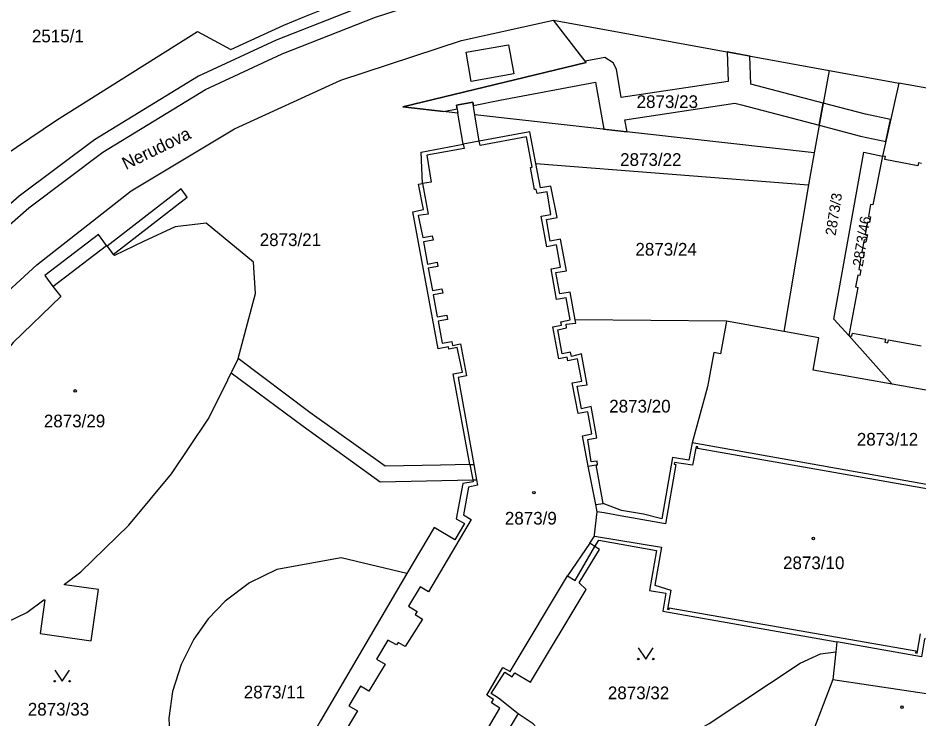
# Model space of a CAD drawing. Extents: x -756746 to -753363, y -1166406 to -1161727.
# Drawn here: x -756300.9 to -756180.3, y -1164964.7 to -1164870.8 of the extents above; entities that cross this region are included whole.
import ezdxf

# ---------------------------------------------------------------- set-up
doc = ezdxf.new("R2010")
doc.units = 0
for name, color, linetype in [('Hranice parcel', 7, 'Continuous'), ('Parcelní čísla', 7, 'Continuous'), ('Pop  PČ popisy', 7, 'Continuous'), ('Vnitřní kresba', 7, 'Continuous'), ('Věcná břemena k části', 7, 'Continuous'), ('Značky budov', 7, 'Continuous'), ('Značky kultur', 7, 'Continuous')]:
    doc.layers.add(name, color=color, linetype=linetype)

msp = doc.modelspace()

# ---------------------------------------------------------------- linework, layer by layer
at = {"layer": 'Hranice parcel'}
for p, q in [((-756241.55, -1164873.83), (-756229.25, -1164871.08)), ((-756229.25, -1164871.08), (-756192.35, -1164877.85)), ((-756192.35, -1164877.85), (-756194.33, -1164888.86)), ((-756183.02, -1164879.52), (-756185.21, -1164889.29)), ((-756155.37, -1164884.5), (-756183.02, -1164879.52)), ((-756240.05, -1164882.06), (-756242.23, -1164882.49)), ((-756242.23, -1164882.49), (-756242.06, -1164883.53)), ((-756239.78, -1164883.78), (-756240.05, -1164882.06)), ((-756241.36, -1164887.72), (-756242.06, -1164883.53)), ((-756239.21, -1164887.32), (-756239.78, -1164883.78)), ((-756194.33, -1164888.86), (-756239.78, -1164883.78)), ((-756232.42, -1164886.06), (-756239.21, -1164887.32)), ((-756231.6, -1164890.28), (-756232.42, -1164886.06)), ((-756194.33, -1164888.86), (-756195.09, -1164893.16)), ((-756230.97, -1164893.56), (-756231.6, -1164890.28)), ((-756231.6, -1164890.28), (-756195.09, -1164893.16)), ((-756195.09, -1164893.16), (-756198.4, -1164912.78)), ((-756226.33, -1164911.23), (-756227.02, -1164907.5)), ((-756226.25, -1164911.68), (-756226.33, -1164911.23)), ((-756206.1, -1164911.41), (-756226.33, -1164911.23)), ((-756198.4, -1164912.78), (-756206.1, -1164911.41)), ((-756189.7, -1164913.31), (-756183.9, -1164919.85)), ((-756240.44, -1164930.6), (-756240.07, -1164932.64)), ((-756191.3, -1164954.33), (-756191.45, -1164955.65)), ((-756191.45, -1164955.65), (-756191.87, -1164959.39)), ((-756191.87, -1164959.39), (-756194.46, -1164966.14)), ((-756191.87, -1164959.39), (-756173.81, -1164962.04))]:
    msp.add_line(p, q, dxfattribs=at)
for points in [[(-756332.73, -1164925.42), (-756326.95, -1164918.66), (-756327.49, -1164913.36), (-756312.07, -1164897.62), (-756304.74, -1164890.5), (-756295.77, -1164884.5), (-756276.91, -1164872.6), (-756272.47, -1164875.04), (-756265.36, -1164871.78), (-756262.76, -1164870.7), (-756260.3, -1164869.73), (-756257.97, -1164868.82), (-756255.56, -1164867.96), (-756253.1, -1164867.15), (-756240.81, -1164863.24), (-756239.69, -1164862.83), (-756238.72, -1164862.02)], [(-756242.06, -1164883.53), (-756249.44, -1164882.7), (-756224.89, -1164876.79), (-756229.25, -1164871.08)], [(-756326.38, -1164933.38), (-756310.7, -1164915.08), (-756298.41, -1164903.86), (-756285.81, -1164893.94), (-756271.95, -1164885.65), (-756257.71, -1164879.12), (-756241.55, -1164873.83)], [(-756192.35, -1164877.85), (-756184.46, -1164879.26), (-756183.02, -1164879.52)], [(-756240.44, -1164930.6), (-756242.68, -1164918.46), (-756241.45, -1164918.21), (-756242.16, -1164914.91), (-756243.26, -1164915.15), (-756243.32, -1164914.83), (-756244.68, -1164915.08), (-756248.07, -1164896.76), (-756246.65, -1164896.47), (-756247.31, -1164893.05), (-756246.77, -1164892.96), (-756246.97, -1164888.76), (-756241.36, -1164887.72)], [(-756189.7, -1164913.31), (-756191.73, -1164911.11), (-756187.68, -1164888.79), (-756185.21, -1164889.29)], [(-756185.21, -1164889.29), (-756186.5, -1164895.84), (-756186.8, -1164895.79), (-756187.09, -1164897.4), (-756186.8, -1164897.45), (-756186.94, -1164898.21), (-756187.23, -1164898.15), (-756187.53, -1164899.76), (-756187.23, -1164899.82), (-756187.37, -1164900.57), (-756187.66, -1164900.52), (-756187.96, -1164902.12), (-756187.66, -1164902.17), (-756187.8, -1164902.92), (-756188.09, -1164902.87), (-756188.39, -1164904.47), (-756188.09, -1164904.52), (-756188.23, -1164905.28), (-756188.52, -1164905.22), (-756188.82, -1164906.82), (-756188.52, -1164906.88), (-756189.7, -1164913.31)], [(-756179.98, -1164890.29), (-756180.37, -1164890.22), (-756180.45, -1164890.61), (-756184.89, -1164889.76), (-756184.81, -1164889.37), (-756185.21, -1164889.29)], [(-756240.44, -1164930.6), (-756244.37, -1164930.66), (-756251.8, -1164930.83), (-756261.87, -1164923.62), (-756271.47, -1164916.38), (-756269.15, -1164907.71), (-756269.4, -1164903.52), (-756275.75, -1164898.27), (-756279.9, -1164898.77), (-756284.16, -1164900.75), (-756288.03, -1164902.62), (-756288.18, -1164902.47), (-756278.28, -1164894.79), (-756279.08, -1164893.7), (-756289, -1164901.35), (-756289.08, -1164901.28), (-756290.18, -1164899.81), (-756297.35, -1164905.28), (-756296.26, -1164906.74), (-756295.22, -1164908.1), (-756301.6, -1164914.27), (-756307.34, -1164921.2), (-756312.21, -1164928.56), (-756314.71, -1164933.55)], [(-756227.02, -1164907.5), (-756228.39, -1164907.75), (-756228.93, -1164904.9), (-756227.53, -1164904.64), (-756228.31, -1164900.41), (-756229.68, -1164900.67), (-756230.18, -1164897.79), (-756228.77, -1164897.52), (-756229.59, -1164893.33), (-756230.97, -1164893.56)], [(-756222.59, -1164935.8), (-756223.54, -1164930.65), (-756223.38, -1164930.62), (-756223.41, -1164930.13), (-756224.22, -1164930.24), (-756224.67, -1164927.22), (-756223.43, -1164927.03), (-756224.19, -1164922.84), (-756225.51, -1164923.14), (-756226.09, -1164920.11), (-756224.74, -1164919.92), (-756225.51, -1164915.76), (-756226.86, -1164916.11), (-756226.96, -1164915.57), (-756228.09, -1164915.78), (-756228.68, -1164912.58), (-756227.49, -1164912.3), (-756227.54, -1164911.8), (-756226.25, -1164911.68)], [(-756206.1, -1164911.41), (-756206.91, -1164915.76), (-756207.78, -1164915.59), (-756208.63, -1164920.21), (-756210.69, -1164927.69)], [(-756183.9, -1164919.85), (-756194.49, -1164917.98), (-756193.73, -1164913.61), (-756198.4, -1164912.78)], [(-756189.7, -1164913.31), (-756189.3, -1164913.39), (-756189.23, -1164912.99), (-756184.81, -1164913.81), (-756184.88, -1164914.21), (-756184.5, -1164914.28), (-756184.42, -1164913.88), (-756180.03, -1164914.7)], [(-756312.02, -1164954.84), (-756307.85, -1164954.28), (-756299.75, -1164950.41), (-756297.47, -1164948.69), (-756297.37, -1164948.71), (-756297.99, -1164953.23), (-756291.13, -1164954.18), (-756290.16, -1164947.31), (-756294.71, -1164946.69), (-756294.7, -1164946.61), (-756292.53, -1164944.94), (-756286.1, -1164938.71), (-756280.39, -1164931.84), (-756275.49, -1164924.52), (-756273.31, -1164920.17), (-756272.42, -1164918.32), (-756262.77, -1164925.47), (-756252.46, -1164932.92), (-756240.07, -1164932.64)], [(-756160.13, -1164924.19), (-756163.99, -1164923.36), (-756183.9, -1164919.85)], [(-756210.69, -1164927.69), (-756211.13, -1164930.02), (-756213.31, -1164929.65), (-756214.73, -1164937.87), (-756217.2, -1164937.24), (-756220.16, -1164936.74), (-756222.59, -1164935.8)], [(-756167.95, -1164937.59), (-756176.44, -1164936.08), (-756176.04, -1164933.86), (-756210.69, -1164927.69)], [(-756240.07, -1164932.64), (-756240.02, -1164932.89), (-756241.37, -1164933.14), (-756242.26, -1164937.87), (-756241.18, -1164938.48), (-756242.47, -1164940.67), (-756245.24, -1164939.04), (-756248.89, -1164945.2)], [(-756223.72, -1164941.55), (-756224.4, -1164941.11), (-756223.78, -1164940.2), (-756223.76, -1164940.02), (-756223.42, -1164936.91), (-756223.6, -1164935.95), (-756222.59, -1164935.8)], [(-756223.72, -1164941.55), (-756223.19, -1164940.7), (-756215.47, -1164942.1), (-756216.38, -1164947.45), (-756214.21, -1164947.82), (-756214.63, -1164950.21), (-756191.3, -1164954.33)], [(-756233.96, -1164963.95), (-756236.61, -1164961.87), (-756237.58, -1164961.25), (-756235.76, -1164958.38), (-756234.79, -1164959), (-756234.43, -1164958.5), (-756232.34, -1164959.75), (-756224.86, -1164947.31), (-756225.8, -1164946.43), (-756223.09, -1164941.96), (-756223.72, -1164941.55)], [(-756248.89, -1164945.2), (-756257.69, -1164943.07), (-756266.27, -1164944.65), (-756269.94, -1164946.45), (-756273.21, -1164948.89), (-756275.49, -1164951.27), (-756277.39, -1164953.97), (-756279.11, -1164957.36), (-756280.27, -1164960.97), (-756280.77, -1164964.53), (-756280.58, -1164968.22), (-756279.9, -1164971.67), (-756278.65, -1164974.95), (-756277.32, -1164977.55), (-756275.66, -1164979.89), (-756273.33, -1164982.48), (-756270.6, -1164984.45), (-756267.97, -1164985.9)], [(-756248.89, -1164945.2), (-756260.43, -1164964.92), (-756267.15, -1164976.56), (-756266.67, -1164977.52), (-756265.67, -1164978.18), (-756259.49, -1164981.93), (-756255.88, -1164984.03), (-756254.66, -1164983.89), (-756254.07, -1164982.09), (-756252.08, -1164983.3), (-756251.55, -1164983.62), (-756251.17, -1164982.99), (-756250.71, -1164983.27), (-756248.28, -1164979.58), (-756248.44, -1164979.48), (-756247.11, -1164977.67), (-756246.79, -1164977.87), (-756246.85, -1164977.97), (-756243.58, -1164979.92), (-756234.09, -1164964.16), (-756233.96, -1164963.95)], [(-756171.77, -1164955.32), (-756179.59, -1164953.94), (-756180, -1164956.32), (-756191.3, -1164954.33)], [(-756234.16, -1164980.09), (-756208.42, -1164965.27), (-756196.24, -1164957.2), (-756193.5, -1164955.92), (-756191.45, -1164955.65)], [(-756234.16, -1164980.09), (-756231.13, -1164978.13), (-756229.75, -1164976.49), (-756228.87, -1164974.54), (-756228.74, -1164972.63), (-756229.37, -1164969.77), (-756230.36, -1164967.11), (-756231.97, -1164965.3), (-756233.96, -1164963.95)]]:
    msp.add_lwpolyline(points, dxfattribs=at)
at = {"layer": 'Vnitřní kresba'}
for p, q in [((-756240.93, -1164875.38), (-756235.28, -1164874.41)), ((-756235.28, -1164874.41), (-756234.58, -1164878.3)), ((-756240.26, -1164879.31), (-756240.93, -1164875.38)), ((-756234.58, -1164878.3), (-756240.26, -1164879.31)), ((-756239.21, -1164887.32), (-756241.36, -1164887.72)), ((-756241.36, -1164887.72), (-756241.2, -1164888.26)), ((-756239.06, -1164887.87), (-756239.21, -1164887.32)), ((-756232.85, -1164886.72), (-756239.06, -1164887.87)), ((-756232.1, -1164890.79), (-756232.85, -1164886.72)), ((-756241.2, -1164888.26), (-756246.22, -1164889.19)), ((-756246.22, -1164889.19), (-756245.62, -1164892.77)), ((-756232.33, -1164890.84), (-756232.1, -1164890.79)), ((-756231.79, -1164893.79), (-756232.33, -1164890.84)), ((-756245.62, -1164892.77), (-756246.77, -1164892.96)), ((-756246.77, -1164892.96), (-756246.02, -1164897.06)), ((-756231.55, -1164893.75), (-756231.79, -1164893.79)), ((-756231.45, -1164894.31), (-756231.55, -1164893.75)), ((-756230.1, -1164894.09), (-756231.45, -1164894.31)), ((-756229.61, -1164897.1), (-756230.1, -1164894.09)), ((-756246.02, -1164897.06), (-756247.36, -1164897.25)), ((-756247.36, -1164897.25), (-756246.76, -1164900.21)), ((-756230.89, -1164897.34), (-756229.61, -1164897.1)), ((-756230.13, -1164901.44), (-756230.89, -1164897.34)), ((-756246.76, -1164900.21), (-756245.48, -1164899.97)), ((-756245.38, -1164900.54), (-756246.66, -1164900.78)), ((-756246.66, -1164900.78), (-756246.11, -1164903.75)), ((-756245.48, -1164899.97), (-756245.38, -1164900.54)), ((-756296.26, -1164906.74), (-756289.08, -1164901.28)), ((-756289, -1164901.35), (-756288.18, -1164902.47)), ((-756228.85, -1164901.2), (-756230.13, -1164901.44)), ((-756228.3, -1164904.17), (-756228.85, -1164901.2)), ((-756246.11, -1164903.75), (-756244.83, -1164903.52)), ((-756244.83, -1164903.52), (-756244.73, -1164904.08)), ((-756244.73, -1164904.08), (-756246.01, -1164904.31)), ((-756246.01, -1164904.31), (-756245.46, -1164907.28)), ((-756229.58, -1164904.4), (-756228.3, -1164904.17)), ((-756228.83, -1164908.5), (-756229.58, -1164904.4)), ((-756245.46, -1164907.28), (-756244.18, -1164907.05)), ((-756244.18, -1164907.05), (-756244.07, -1164907.64)), ((-756244.07, -1164907.64), (-756245.35, -1164907.87)), ((-756245.35, -1164907.87), (-756244.81, -1164910.84)), ((-756227.55, -1164908.26), (-756228.83, -1164908.5)), ((-756227, -1164911.23), (-756227.55, -1164908.26)), ((-756244.81, -1164910.84), (-756243.53, -1164910.61)), ((-756243.53, -1164910.61), (-756243.43, -1164911.16)), ((-756243.43, -1164911.16), (-756244.7, -1164911.39)), ((-756244.7, -1164911.39), (-756244.16, -1164914.35)), ((-756229.32, -1164912.14), (-756228.19, -1164911.93)), ((-756228.28, -1164911.47), (-756227, -1164911.23)), ((-756228.19, -1164911.93), (-756228.28, -1164911.47)), ((-756228.53, -1164916.42), (-756229.32, -1164912.14)), ((-756244.16, -1164914.35), (-756242.88, -1164914.13)), ((-756242.88, -1164914.13), (-756242.79, -1164914.64)), ((-756242.79, -1164914.64), (-756241.68, -1164914.44)), ((-756241.68, -1164914.44), (-756240.9, -1164918.72)), ((-756271.47, -1164916.38), (-756272.42, -1164918.32)), ((-756227.4, -1164916.21), (-756228.53, -1164916.42)), ((-756227.31, -1164916.7), (-756227.4, -1164916.21)), ((-756226.03, -1164916.46), (-756227.31, -1164916.7)), ((-756225.46, -1164919.43), (-756226.03, -1164916.46)), ((-756240.9, -1164918.72), (-756242, -1164918.92)), ((-756242, -1164918.92), (-756239.93, -1164930.59)), ((-756226.73, -1164919.67), (-756225.46, -1164919.43)), ((-756225.94, -1164923.78), (-756226.73, -1164919.67)), ((-756224.67, -1164923.54), (-756225.94, -1164923.78)), ((-756224.1, -1164926.5), (-756224.67, -1164923.54)), ((-756225.37, -1164926.75), (-756224.1, -1164926.5)), ((-756224.59, -1164930.83), (-756225.37, -1164926.75)), ((-756210.14, -1164928.19), (-756210.65, -1164930.68)), ((-756209.93, -1164928.23), (-756210.14, -1164928.19)), ((-756209.97, -1164928.45), (-756209.93, -1164928.23)), ((-756176.97, -1164934.26), (-756209.97, -1164928.45)), ((-756240.44, -1164930.6), (-756239.93, -1164930.59)), ((-756239.93, -1164930.59), (-756239.57, -1164932.62)), ((-756224.59, -1164930.83), (-756223.54, -1164930.65)), ((-756223.6, -1164935.95), (-756224.59, -1164930.83)), ((-756212.88, -1164930.58), (-756214.24, -1164938.53)), ((-756213.06, -1164930.33), (-756213.1, -1164930.54)), ((-756213.1, -1164930.54), (-756212.88, -1164930.58)), ((-756210.65, -1164930.68), (-756213.06, -1164930.33)), ((-756240.65, -1164933.62), (-756241.32, -1164937.32)), ((-756239.44, -1164933.37), (-756240.65, -1164933.62)), ((-756240.07, -1164932.64), (-756239.57, -1164932.62)), ((-756239.57, -1164932.62), (-756239.44, -1164933.37)), ((-756241.32, -1164937.32), (-756240.27, -1164937.94)), ((-756222.47, -1164937.08), (-756223.42, -1164936.91)), ((-756220.31, -1164937.46), (-756222.47, -1164937.08)), ((-756240.27, -1164937.94), (-756245.98, -1164947.64)), ((-756217.28, -1164937.99), (-756220.31, -1164937.46)), ((-756214.24, -1164938.53), (-756217.28, -1164937.99)), ((-756223.78, -1164940.2), (-756214.77, -1164941.65)), ((-756224.4, -1164941.11), (-756227.37, -1164945.48)), ((-756226.34, -1164946.1), (-756223.72, -1164941.55)), ((-756214.77, -1164941.65), (-756215.68, -1164946.76)), ((-756235.07, -1164958.31), (-756227.37, -1164945.48)), ((-756227.37, -1164945.48), (-756226.34, -1164946.1)), ((-756215.68, -1164946.76), (-756213.54, -1164947.41)), ((-756247.12, -1164946.98), (-756248.66, -1164949.55)), ((-756245.98, -1164947.64), (-756247.12, -1164946.98)), ((-756213.54, -1164947.41), (-756214, -1164949.95)), ((-756248.66, -1164949.55), (-756247.49, -1164950.25)), ((-756247.49, -1164950.25), (-756247.75, -1164950.69)), ((-756214, -1164949.95), (-756213.78, -1164949.99)), ((-756213.78, -1164949.99), (-756213.75, -1164949.77)), ((-756213.75, -1164949.77), (-756180.75, -1164955.55)), ((-756246.81, -1164951.28), (-756249.11, -1164954.94)), ((-756247.75, -1164950.69), (-756246.81, -1164951.28)), ((-756251.42, -1164954.11), (-756252.93, -1164956.66)), ((-756250.25, -1164954.74), (-756251.42, -1164954.11)), ((-756180.55, -1164955.85), (-756180.1, -1164953.26)), ((-756250.05, -1164954.41), (-756250.25, -1164954.74)), ((-756249.11, -1164954.94), (-756250.05, -1164954.41)), ((-756180.75, -1164955.55), (-756180.8, -1164955.81)), ((-756180.8, -1164955.81), (-756180.55, -1164955.85)), ((-756251.8, -1164957.34), (-756253.96, -1164960.95)), ((-756252.93, -1164956.66), (-756251.8, -1164957.34)), ((-756238.19, -1164961.46), (-756236.03, -1164957.75)), ((-756236.03, -1164957.75), (-756235.07, -1164958.31)), ((-756255.09, -1164960.28), (-756256.64, -1164962.88)), ((-756253.96, -1164960.95), (-756255.09, -1164960.28)), ((-756237.29, -1164962.06), (-756238.19, -1164961.46)), ((-756237.56, -1164962.51), (-756237.29, -1164962.06)), ((-756236.42, -1164963.19), (-756237.56, -1164962.51)), ((-756255.51, -1164963.55), (-756259.26, -1164969.83)), ((-756256.64, -1164962.88), (-756255.51, -1164963.55)), ((-756237.96, -1164965.78), (-756236.42, -1164963.19))]:
    msp.add_line(p, q, dxfattribs=at)
at = {"layer": 'Věcná břemena k části'}
msp.add_lwpolyline([(-756311.02, -1164906.32), (-756299.51, -1164896.24), (-756289.57, -1164888.76), (-756275.83, -1164880.37), (-756265.58, -1164875.62), (-756253.08, -1164870.69), (-756239.22, -1164866.18), (-756239.84, -1164864.28), (-756253.76, -1164868.81), (-756266.36, -1164873.78), (-756276.77, -1164878.61), (-756290.69, -1164887.1), (-756300.77, -1164894.68), (-756312.38, -1164904.86)], dxfattribs=at)
for points in [[(-756225.02, -1164876.61), (-756224.89, -1164876.79), (-756249.44, -1164882.7), (-756243.99, -1164883.31), (-756242.15, -1164882.95), (-756242.23, -1164882.49), (-756240.05, -1164882.06), (-756239.98, -1164882.53), (-756236.44, -1164881.83), (-756223.63, -1164879.41), (-756222.51, -1164885.71), (-756219.37, -1164886.06), (-756219.69, -1164884.43), (-756204.97, -1164882.2), (-756204.07, -1164882.45), (-756193.67, -1164885.17), (-756193.13, -1164882.21), (-756202.85, -1164879.68), (-756202.96, -1164875.9), (-756205.98, -1164875.35), (-756205.86, -1164879.3), (-756220.2, -1164881.47), (-756220.83, -1164877.65), (-756221.28, -1164876.83), (-756222.37, -1164876.11)], [(-756193.67, -1164885.17), (-756188.15, -1164886.61), (-756184.77, -1164887.34), (-756184.12, -1164884.41), (-756187.47, -1164883.69), (-756193.13, -1164882.21)]]:
    msp.add_lwpolyline(points, close=True, dxfattribs=at)
at = {"layer": 'Značky budov'}
for centre in [(-756293.29, -1164920.74), (-756231.87, -1164934.36), (-756194.46, -1164940.5), (-756182.59, -1164963.08)]:
    msp.add_circle(centre, 0.175, dxfattribs=at)
at = {"layer": 'Značky kultur'}
for points in [[(-756217.9, -1164955.13), (-756216.9, -1164956.63), (-756215.9, -1164955.13)], [(-756296.03, -1164958.1), (-756295.03, -1164959.6), (-756294.03, -1164958.1)]]:
    msp.add_lwpolyline(points, dxfattribs=at)
for centre in [(-756217.9, -1164956.63), (-756215.9, -1164956.63), (-756296.03, -1164959.6), (-756294.03, -1164959.6)]:
    msp.add_circle(centre, 0.1, dxfattribs=at)

# ---------------------------------------------------------------- texts
at = {"layer": 'Parcelní čísla'}
for s, p in [('2515/1', (-756299.08, -1164874.07)), ('2873/23', (-756218.12, -1164882.86)), ('2873/22', (-756220.33, -1164890.61)), ('2873/21', (-756268.58, -1164901.34)), ('2873/24', (-756218.28, -1164902.62)), ('2873/20', (-756221.79, -1164923.63)), ('2873/29', (-756297.48, -1164925.61)), ('2873/12', (-756188.64, -1164928.06)), ('2873/9', (-756235.76, -1164938.63)), ('2873/10', (-756198.52, -1164944.6)), ('2873/11', (-756270.72, -1164961.9)), ('2873/32', (-756221.97, -1164962.01)), ('2873/33', (-756299.63, -1164964.2))]:
    msp.add_text(s, height=1.7, dxfattribs=at).set_placement(p)
for s, p in [('2873/3', (-756191.49, -1164900.02)), ('2873/46', (-756187.84, -1164904.16))]:
    msp.add_text(s, height=1.4, rotation=81, dxfattribs=at).set_placement(p)
at = {"layer": 'Pop  PČ popisy'}
msp.add_text('Nerudova', height=1.7, rotation=26, dxfattribs=at).set_placement((-756286.49, -1164891.18))

doc.saveas('drawing.dxf')
